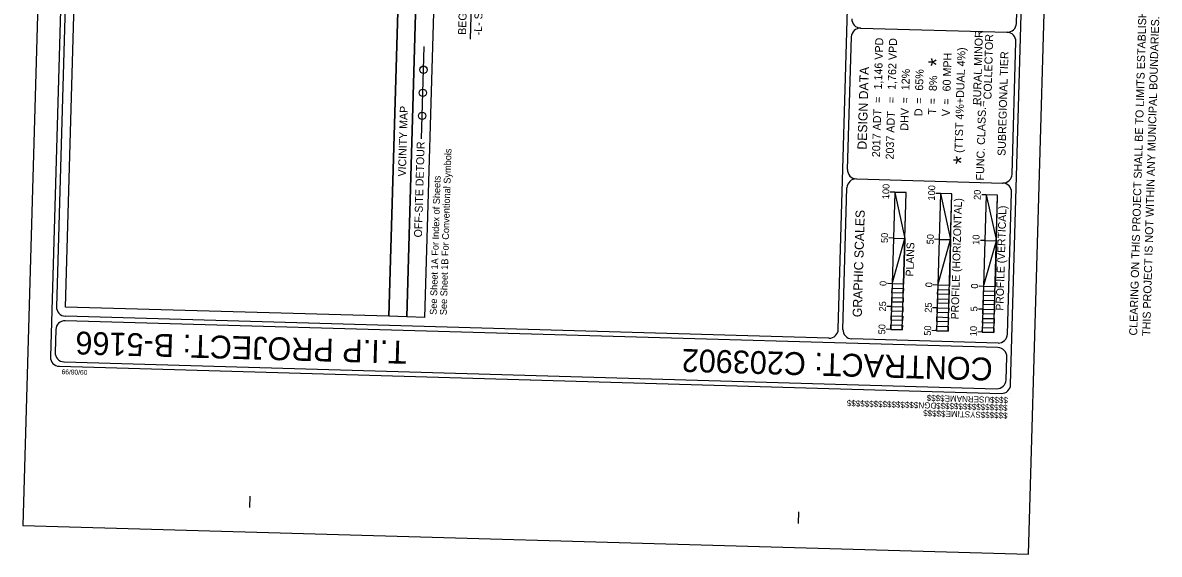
# Model space of a CAD drawing. Extents: x 2097846 to 2099709, y 989477 to 992073.
# Drawn here: x 2097846 to 2099709, y 989477 to 990349 of the extents above; entities that cross this region are included whole.
import ezdxf

# ---------------------------------------------------------------- set-up
doc = ezdxf.new("R2010")
doc.units = 0
for name, color, linetype in [('Prop DSN Text', 7, 'Continuous'), ('Prop Horizontal Alignment Station Label', 7, 'Continuous'), ('Sheet Data Field CELL', 7, 'Continuous'), ('Sheet Title CELL', 7, 'Continuous'), ('Stewart Plot Border Xerox6279 and LJ5000', 7, 'Continuous')]:
    doc.layers.add(name, color=color, linetype=linetype)

msp = doc.modelspace()

# ---------------------------------------------------------------- linework, layer by layer
at = {"layer": 'Prop Horizontal Alignment Station Label'}
msp.add_lwpolyline([(2098580.1, 990321.9), (2098588.3, 990605.2), (2098737.1, 990658.5)], dxfattribs=at)
at = {"layer": 'Sheet Data Field CELL'}
for p, q in [((2099275.6, 990070.7), (2099268.1, 990070.9)), ((2099273.5, 989995.7), (2099266, 989995.9)), ((2099270.2, 989883.2), (2099262.8, 989883.5)), ((2099269.2, 989845.8), (2099261.7, 989846)), ((2099465.1, 989740.3), (2099465.1, 989740.3))]:
    msp.add_line(p, q, dxfattribs=at)
at = {"layer": 'Sheet Title CELL'}
for p, q in [((2099183, 989846), (2099244.4, 991975.1)), ((2099219.8, 990340.1), (2099459.7, 990333.2)), ((2099198.1, 990108.1), (2099204.4, 990325.6)), ((2098499.6, 990158.2), (2098504, 990309.6)), ((2099212.7, 990092.7), (2099452.6, 990085.8)), ((2099190.6, 989845.8), (2099197.2, 990078.2)), ((2099275.6, 990070.6), (2099268.2, 990070.9)), ((2099275.6, 990070.6), (2099269.2, 989845.7)), ((2099294.4, 990070.1), (2099275.6, 990070.6)), ((2099287.9, 989845.2), (2099294.4, 990070.1)), ((2099350.6, 990068.5), (2099343.1, 990068.7)), ((2099350.6, 990068.5), (2099343.1, 990068.7)), ((2099350.6, 990068.5), (2099344.2, 989843.6)), ((2099350.6, 990068.5), (2099344.2, 989843.6)), ((2099369.4, 990067.9), (2099350.6, 990068.5)), ((2099362.9, 989843), (2099369.4, 990067.9)), ((2099425.6, 990066.3), (2099418.1, 990066.5)), ((2099425.6, 990066.3), (2099418.1, 990066.5)), ((2099425.6, 990066.3), (2099418.1, 990066.5)), ((2099425.6, 990066.3), (2099419.1, 989841.4)), ((2099425.6, 990066.3), (2099419.1, 989841.4)), ((2099425.6, 990066.3), (2099419.1, 989841.4)), ((2099444.3, 990065.8), (2099425.6, 990066.3)), ((2099437.8, 989840.9), (2099444.3, 990065.8)), ((2099273.5, 989995.7), (2099266, 989995.9)), ((2099273.5, 989995.7), (2099292.2, 989995.1)), ((2099348.5, 989993.5), (2099341, 989993.7)), ((2099348.5, 989993.5), (2099341, 989993.7)), ((2099348.5, 989993.5), (2099367.2, 989993)), ((2099423.4, 989991.4), (2099415.9, 989991.6)), ((2099423.4, 989991.4), (2099415.9, 989991.6)), ((2099423.4, 989991.4), (2099415.9, 989991.6)), ((2099423.4, 989991.4), (2099442.2, 989990.8)), ((2099271.3, 989920.7), (2099263.9, 989920.9)), ((2099346.3, 989918.5), (2099338.8, 989918.8)), ((2099346.3, 989918.5), (2099338.8, 989918.8)), ((2099421.3, 989916.4), (2099413.8, 989916.6)), ((2099421.3, 989916.4), (2099413.8, 989916.6)), ((2099421.3, 989916.4), (2099413.8, 989916.6)), ((2099270.7, 989898.2), (2099289.4, 989897.7)), ((2099345.7, 989896.1), (2099364.4, 989895.5)), ((2099420.6, 989893.9), (2099439.4, 989893.4)), ((2099167.6, 989831.4), (2097915.6, 989867.5)), ((2099270.3, 989883.2), (2099262.8, 989883.4)), ((2099345.2, 989881.1), (2099337.7, 989881.3)), ((2099345.2, 989881.1), (2099337.7, 989881.3)), ((2099420.2, 989878.9), (2099412.7, 989879.1)), ((2099420.2, 989878.9), (2099412.7, 989879.1)), ((2099420.2, 989878.9), (2099412.7, 989879.1)), ((2099444.8, 989815.9), (2097915.4, 989860)), ((2099445, 989823.4), (2099205.1, 989830.3)), ((2099269.2, 989845.7), (2099261.7, 989846)), ((2099261.7, 989846), (2099261.7, 989846)), ((2099269.2, 989845.7), (2099287.9, 989845.2)), ((2099269.2, 989845.7), (2099269.2, 989845.7)), ((2099344.2, 989843.6), (2099336.6, 989843.8)), ((2099344.2, 989843.6), (2099336.6, 989843.8)), ((2099336.6, 989843.8), (2099336.6, 989843.8)), ((2099344.2, 989843.6), (2099362.9, 989843)), ((2099344.2, 989843.6), (2099344.2, 989843.6)), ((2099344.2, 989843.6), (2099344.2, 989843.6)), ((2099419.1, 989841.4), (2099411.6, 989841.6)), ((2099419.1, 989841.4), (2099411.6, 989841.6)), ((2099419.1, 989841.4), (2099411.6, 989841.6)), ((2099411.6, 989841.6), (2099411.6, 989841.6)), ((2099419.1, 989841.4), (2099437.8, 989840.9)), ((2099419.1, 989841.4), (2099419.1, 989841.4)), ((2099419.1, 989841.4), (2099419.1, 989841.4)), ((2099419.1, 989841.4), (2099419.1, 989841.4)), ((2099465.1, 989740.3), (2099465.1, 989740.3)), ((2099465.1, 989740.3), (2099465.1, 989740.3)), ((2099465.1, 989740.3), (2099465.1, 989740.3)), ((2099465.1, 989740.3), (2099465.1, 989740.3)), ((2098218, 989553.4), (2098218.5, 989572.1)), ((2098218, 989553.4), (2098218.5, 989572.1)), ((2099117.6, 989527.5), (2099118.1, 989546.2)), ((2099117.6, 989527.5), (2099118.1, 989546.2))]:
    msp.add_line(p, q, dxfattribs=at)
for points in [[(2097955.1, 992019.7), (2097891.2, 989800.6)], [(2097962.4, 992012), (2097901.1, 989882.9)], [(2099465.6, 989755.3), (2099529.5, 991974.4)], [(2099475.1, 990347.8), (2099491.5, 990917.5)], [(2099468, 990100.4), (2099474.2, 990317.8)], [(2099460.4, 989838), (2099467.1, 990070.4)], [(2097900, 989845.4), (2097898.9, 989807.9)], [(2099458.3, 989763), (2099459.3, 989800.5)], [(2097905.8, 989785.2), (2099450.1, 989740.7)], [(2097905.8, 989785.2), (2099450.1, 989740.7)], [(2097913.5, 989792.5), (2099442.8, 989748.4)]]:
    msp.add_lwpolyline(points, dxfattribs=at)
for points in [[(2097916, 989882.5), (2097932.5, 990456.9), (2098462.8, 990441.6), (2098446.2, 989867.2)], [(2098446.2, 989867.2), (2098462.8, 990441.6), (2098492, 990440.8), (2098475.4, 989866.4)], [(2098475.4, 989866.4), (2098492, 990440.8), (2098521.2, 990439.9), (2098504.6, 989865.5)], [(2099275.6, 990070.6), (2099292.2, 989995.1), (2099294.4, 990070.1)], [(2099350.6, 990068.5), (2099367.2, 989993), (2099369.4, 990067.9)], [(2099425.6, 990066.3), (2099442.2, 989990.8), (2099444.3, 990065.8)], [(2099271.3, 989920.7), (2099292.2, 989995.1), (2099290.1, 989920.2)], [(2099346.3, 989918.5), (2099367.2, 989993), (2099365.1, 989918)], [(2099421.3, 989916.4), (2099442.2, 989990.8), (2099440, 989915.8)], [(2099270.9, 989905.7), (2099271.1, 989913.2), (2099289.9, 989912.7), (2099289.6, 989905.2)], [(2099345.9, 989903.6), (2099346.1, 989911.1), (2099364.8, 989910.5), (2099364.6, 989903)], [(2099420.9, 989901.4), (2099421.1, 989908.9), (2099439.8, 989908.4), (2099439.6, 989900.9)], [(2099270.5, 989890.7), (2099270.7, 989898.2), (2099289.4, 989897.7), (2099289.2, 989890.2)], [(2099345.5, 989888.6), (2099345.7, 989896.1), (2099364.4, 989895.5), (2099364.2, 989888)], [(2099420.4, 989886.4), (2099420.6, 989893.9), (2099439.4, 989893.4), (2099439.1, 989885.9)], [(2099269.6, 989860.7), (2099269.8, 989868.2), (2099288.6, 989867.7), (2099288.4, 989860.2)], [(2099270.1, 989875.7), (2099270.3, 989883.2), (2099289, 989882.7), (2099288.8, 989875.2)], [(2099345, 989873.6), (2099345.2, 989881.1), (2099364, 989880.5), (2099363.8, 989873)], [(2099420, 989871.4), (2099420.2, 989878.9), (2099438.9, 989878.4), (2099438.7, 989870.9)], [(2099269.2, 989845.7), (2099269.4, 989853.2), (2099288.1, 989852.7), (2099287.9, 989845.2)], [(2099344.2, 989843.6), (2099344.4, 989851.1), (2099363.1, 989850.5), (2099362.9, 989843)], [(2099344.6, 989858.6), (2099344.8, 989866.1), (2099363.5, 989865.5), (2099363.3, 989858)], [(2099419.1, 989841.4), (2099419.3, 989848.9), (2099438.1, 989848.4), (2099437.8, 989840.9)], [(2099419.5, 989856.4), (2099419.8, 989863.9), (2099438.5, 989863.4), (2099438.3, 989855.9)]]:
    msp.add_lwpolyline(points, close=True, dxfattribs=at)
for centre in [(2098502.9, 990271.8), (2098501.8, 990233.9), (2098500.7, 990196.1)]:
    msp.add_circle(centre, 6.13, dxfattribs=at)
for centre, start, end in [((2099220.1, 990355.1), 178.35, 268.35), ((2099219.3, 990325.1), 88.35, 178.35), ((2099460, 990348.2), 268.35, 358.35), ((2099459.2, 990318.2), 358.35, 88.35), ((2099212.2, 990077.7), 88.35, 178.35), ((2099213, 990107.7), 178.35, 268.35), ((2099452.9, 990100.8), 268.35, 358.35), ((2099452.1, 990070.8), 358.35, 88.35), ((2097916, 989882.5), 178.35, 268.35), ((2097914.9, 989845), 88.35, 178.35), ((2099168, 989846.4), 268.35, 358.35), ((2099205.5, 989845.3), 178.35, 268.35), ((2099445.4, 989838.4), 268.35, 358.35), ((2099444.3, 989800.9), 358.35, 88.35), ((2097906.1, 989800.2), 178.35, 268.35), ((2097913.8, 989807.5), 178.35, 268.35), ((2099443.2, 989763.4), 268.35, 358.35), ((2099450.5, 989755.7), 268.35, 358.35)]:
    msp.add_arc(centre, 15, start, end, dxfattribs=at)
at = {"layer": 'Stewart Plot Border Xerox6279 and LJ5000'}
msp.add_lwpolyline([(2099495, 989476.8), (2099568.5, 992025.8), (2097919.2, 992073.3), (2097845.7, 989524.3)], close=True, dxfattribs=at)

# ---------------------------------------------------------------- texts
at = {"layer": 'Prop DSN Text'}
msp.add_text('VICINITY MAP', height=13.001, rotation=88.3496, dxfattribs=at).set_placement((2098473.9, 990096.4))
at = {"layer": 'Prop Horizontal Alignment Station Label'}
for s, p in [('BEGIN TIP PROJECT B-5166', (2098572.5, 990328.9)), ('-L- STA. 12+00.00', (2098598.5, 990328.1))]:
    msp.add_text(s, height=13, rotation=88.3496, dxfattribs=at).set_placement(p)
at = {"layer": 'Sheet Data Field CELL'}
for s, height, rotation, p in [('CLEARING ON THIS PROJECT SHALL BE TO LIMITS ESTABLISHED USING METHOD III.', 13.125, 88.3568, (2099673, 989835.6)), ('THIS PROJECT IS NOT WITHIN ANY MUNICIPAL BOUNDARIES.', 13.125, 88.3568, (2099694.3, 989834.9)), ('RURAL MINOR', 13.125, 88.35, (2099416.7, 990213.6)), ('1,146 VPD', 13.13, 88.35, (2099254.4, 990239.2)), ('1,762 VPD', 13.13, 88.35, (2099277, 990238.6)), ('COLLECTOR', 13.13, 88.35, (2099434.1, 990222.9)), ('60 MPH', 13.13, 88.35, (2099367, 990236)), ('(TTST 4%+DUAL 4%)', 13.125, 88.35, (2099386.6, 990135.2)), ('SUBREGIONAL TIER', 13.125, 88.35, (2099457.1, 990130.2)), ('*', 26.3, 88.35, (2099356.8, 990276.9)), ('12%', 13.13, 88.35, (2099299.5, 990237.9)), ('65%', 13.13, 88.35, (2099322, 990237.3)), ('8%', 13.13, 88.35, (2099344.5, 990236.6)), ('=', 13.1, 88.35, (2099253.8, 990217.4)), ('=', 13.1, 88.35, (2099276.3, 990216.8)), ('=', 13.1, 88.35, (2099298.9, 990216.1)), ('=', 13.1, 88.35, (2099321.3, 990215.5)), ('=', 13.1, 88.35, (2099343.8, 990214.8)), ('=', 13.1, 88.35, (2099366.3, 990214.2)), ('2017 ADT ', 13.13, 88.35, (2099251.3, 990128.1)), ('2037 ADT ', 13.13, 88.35, (2099273.7, 990124.3)), ('DHV', 13.13, 88.35, (2099297.6, 990171.6)), ('D', 13.1, 88.35, (2099320.8, 990195.4)), ('T', 13.1, 88.35, (2099343.3, 990198)), ('V', 13.1, 88.35, (2099365.8, 990195.2)), ('FUNC. CLASS.=', 13.125, 88.35, (2099421.7, 990089.9)), ('*', 26.3, 88.35, (2099397.7, 990116)), ('100', 11.25, 88.35, (2099266.3, 990059.3)), ('100', 11.25, 88.35, (2099341.3, 990057.1)), ('20', 11.25, 88.35, (2099416.3, 990058)), ('50', 11.25, 88.35, (2099264.2, 989987.4)), ('50', 11.25, 88.35, (2099339.2, 989985.2)), ('10', 11.25, 88.35, (2099414.2, 989984.4)), ('25', 11.25, 88.35, (2099261, 989875.1)), ('25', 11.25, 88.35, (2099336, 989873)), ('5', 11.3, 88.35, (2099411.1, 989875.2)), ('50', 11.25, 88.35, (2099259.9, 989837.5)), ('50', 11.25, 88.35, (2099334.9, 989835.3)), ('10', 11.25, 88.35, (2099409.9, 989834.5))]:
    msp.add_text(s, height=height, rotation=rotation, dxfattribs=at).set_placement(p)
at = {"layer": 'Sheet Title CELL'}
for s, height, rotation, p in [('DESIGN DATA', 14.999, 88.35, (2099229.3, 990140.5)), ('OFF-SITE DETOUR', 13.001, 88.3496, (2098500.3, 989996.5)), ('See Sheet 1B For Conventional Symbols', 11.25, 88.35, (2098540.9, 989869)), ('See Sheet 1A For Index of Sheets', 11.25, 88.35, (2098524.4, 989869.5)), ('PROFILE (HORIZONTAL)', 12.749, 88.35, (2099380.2, 989862.1)), ('GRAPHIC SCALES', 14.999, 88.35, (2099221.4, 989865.6)), ('PROFILE (VERTICAL)', 12.749, 88.35, (2099453.7, 989876.4)), ('PLANS', 12.75, 88.35, (2099306.2, 989932.5)), ('0', 11.3, 88.35, (2099262, 989916.8)), ('0', 11.3, 88.35, (2099337, 989914.7)), ('0', 11.3, 88.35, (2099337.2, 989914.7)), ('0', 11.3, 88.35, (2099411.9, 989912.5)), ('0', 11.3, 88.35, (2099412.2, 989912.5)), ('0', 11.3, 88.35, (2099412.2, 989912.5)), ('T.I.P PROJECT: B-5166', 37.5, 178.35, (2098476, 989826.7)), ('CONTRACT: C203902', 37.5, 178.35, (2099436.7, 989799.1)), ('09/08/99', 7.88, 178.35, (2097951.9, 989779)), ('$$$$USERNAME$$$$', 9.844, 178.35, (2099461.4, 989734.4)), ('$$$$$$$$$$$$$$$$DGN$$$$$$$$$$$$$$$$', 9.844, 178.35, (2099460.8, 989722.1)), ('$$$$$$SYSTIME$$$$$', 9.844, 178.35, (2099460.8, 989709.3))]:
    msp.add_text(s, height=height, rotation=rotation, dxfattribs=at).set_placement(p)

doc.saveas('drawing.dxf')
